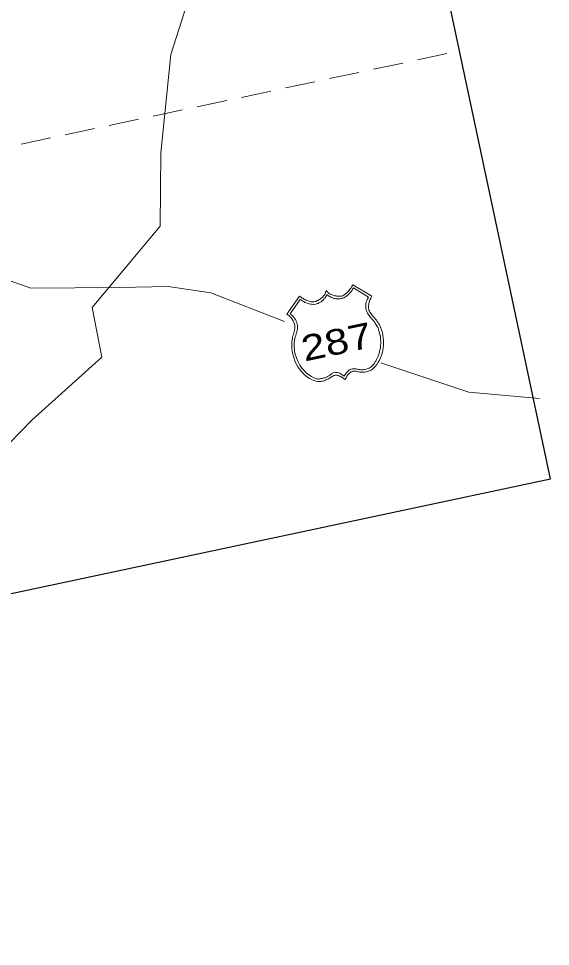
# Model space of a CAD drawing. Extents: x 2357218 to 2371708, y 6973728 to 6980157.
# Drawn here: x 2357673 to 2357779.4, y 6974407.9 to 6974593.4 of the extents above; entities that cross this region are included whole.
import ezdxf

# ---------------------------------------------------------------- set-up
doc = ezdxf.new("R2010")
doc.units = 0
doc.header["$LTSCALE"] = 2
doc.linetypes.add('MEDIUM_DASHED', pattern=[4.5, 3, -1.5])
doc.layers.add('62', color=7, linetype='Continuous', lineweight=13)
doc.layers.add('63', color=7, linetype='Continuous', lineweight=13)

msp = doc.modelspace()

# ---------------------------------------------------------------- linework, layer by layer
at = {"layer": '62', "linetype": 'MEDIUM_DASHED'}
msp.add_line((2357321.423, 6974493.477), (2357761.192, 6974586.953), dxfattribs=at)
at = {"layer": '62'}
for p, q in [((2357711.499, 6974538.57), (2357726.196, 6974532.859)), ((2357763.074, 6974518.776), (2357745.43, 6974524.617)), ((2357777.175, 6974517.491), (2357763.074, 6974518.776))]:
    msp.add_line(p, q, dxfattribs=at)
at = {"layer": '62', "lineweight": 25}
msp.add_lwpolyline([(2357242.867, 6974863.05), (2357339.603, 6974407.945), (2357779.37, 6974501.42), (2357682.634, 6974956.528)], dxfattribs=at)
at = {"layer": '62'}
for points in [[(2357711.499, 6974538.57), (2357702.972, 6974539.842), (2357693.168, 6974539.642), (2357675.502, 6974539.523), (2357664.168, 6974543.509), (2357656.491, 6974546.383), (2357646.543, 6974550.319), (2357635.988, 6974557.671), (2357627.86, 6974566.366), (2357619.672, 6974576.31), (2357608.58, 6974587.803), (2357599.534, 6974594.644), (2357592.196, 6974601.778), (2357583.834, 6974610.927), (2357578.923, 6974614.877), (2357569.363, 6974625.866)], [(2357712.856, 6974614.337), (2357709.274, 6974604.465), (2357703.489, 6974586.211), (2357701.445, 6974566.614), (2357701.343, 6974551.94), (2357687.74, 6974535.638), (2357689.697, 6974525.767), (2357675.675, 6974513.172), (2357664.632, 6974501.808), (2357650.419, 6974491.402), (2357629.375, 6974482.602), (2357611.62, 6974474.364), (2357592.404, 6974464.761), (2357580.771, 6974459.205)], [(2357726.648, 6974534.312), (2357729.214, 6974537.917), (2357729.429, 6974537.779), (2357729.646, 6974537.618), (2357729.876, 6974537.506), (2357730.068, 6974537.362), (2357730.302, 6974537.252), (2357730.505, 6974537.155), (2357730.708, 6974537.062), (2357730.934, 6974536.971), (2357731.108, 6974536.915), (2357731.324, 6974536.87), (2357731.519, 6974536.819), (2357731.728, 6974536.817), (2357731.913, 6974536.81), (2357732.074, 6974536.802), (2357732.296, 6974536.846), (2357732.494, 6974536.888), (2357732.617, 6974536.961), (2357732.76, 6974537.039), (2357732.932, 6974537.097), (2357733.094, 6974537.201), (2357733.258, 6974537.305), (2357733.392, 6974537.425), (2357733.556, 6974537.529), (2357733.711, 6974537.653), (2357733.838, 6974537.818), (2357733.986, 6974537.987), (2357734.112, 6974538.152), (2357734.242, 6974538.294), (2357734.32, 6974538.474), (2357734.418, 6974538.655), (2357734.443, 6974538.866), (2357734.52, 6974539.044), (2357734.662, 6974538.915), (2357734.815, 6974538.74), (2357734.984, 6974538.592), (2357735.145, 6974538.486), (2357735.333, 6974538.365), (2357735.535, 6974538.27), (2357735.712, 6974538.195), (2357735.912, 6974538.12), (2357736.109, 6974538.049), (2357736.289, 6974537.973), (2357736.518, 6974537.973), (2357736.693, 6974537.919), (2357736.943, 6974537.926), (2357737.107, 6974537.915), (2357737.336, 6974537.917), (2357737.518, 6974537.933), (2357737.671, 6974537.967), (2357737.863, 6974538.031), (2357737.983, 6974538.124), (2357738.169, 6974538.209), (2357738.333, 6974538.315), (2357738.468, 6974538.436), (2357738.605, 6974538.555), (2357738.779, 6974538.708), (2357738.905, 6974538.873), (2357739.056, 6974539.019), (2357739.178, 6974539.207), (2357739.347, 6974539.381), (2357739.471, 6974539.567), (2357739.607, 6974539.782), (2357739.725, 6974539.991), (2357739.868, 6974540.182), (2357743.683, 6974537.933), (2357743.461, 6974537.563), (2357743.241, 6974537.195), (2357743.121, 6974536.779), (2357743.052, 6974536.35), (2357742.977, 6974535.942), (2357742.979, 6974535.598), (2357743.042, 6974535.312), (2357743.084, 6974535.115), (2357743.167, 6974534.946), (2357743.275, 6974534.765), (2357743.377, 6974534.601), (2357743.512, 6974534.4), (2357743.668, 6974534.204), (2357743.826, 6974534.007), (2357744.011, 6974533.794), (2357744.193, 6974533.58), (2357744.381, 6974533.342), (2357744.565, 6974533.129), (2357744.736, 6974532.865), (2357744.897, 6974532.646), (2357745.036, 6974532.423), (2357745.175, 6974532.201), (2357745.298, 6974531.95), (2357745.392, 6974531.719), (2357745.576, 6974531.181), (2357745.762, 6974530.645), (2357745.867, 6974530.139), (2357745.913, 6974529.597), (2357745.982, 6974529.06), (2357745.997, 6974528.555), (2357745.967, 6974528.044), (2357745.915, 6974527.528), (2357745.861, 6974527.034), (2357745.738, 6974526.523)], [(2357744.731, 6974525.528), (2357744.882, 6974525.789), (2357744.994, 6974526.136), (2357745.103, 6974526.48), (2357745.209, 6974526.848), (2357745.289, 6974527.232), (2357745.364, 6974527.64), (2357745.417, 6974528.041), (2357745.436, 6974528.484), (2357745.454, 6974528.947), (2357745.408, 6974529.375), (2357745.374, 6974529.85), (2357745.28, 6974530.315), (2357745.154, 6974530.792), (2357745.02, 6974531.202), (2357744.893, 6974531.588), (2357744.713, 6974531.894), (2357744.548, 6974532.227), (2357744.351, 6974532.509), (2357744.181, 6974532.772), (2357743.987, 6974533.029), (2357743.777, 6974533.259), (2357743.568, 6974533.492), (2357743.388, 6974533.685), (2357743.227, 6974533.903), (2357743.066, 6974534.121), (2357742.898, 6974534.361), (2357742.787, 6974534.567), (2357742.669, 6974534.797), (2357742.568, 6974535.051), (2357742.481, 6974535.355), (2357742.477, 6974535.699), (2357742.473, 6974536.043), (2357742.491, 6974536.392), (2357742.548, 6974536.771), (2357742.663, 6974537.096), (2357742.823, 6974537.429), (2357742.981, 6974537.761), (2357739.973, 6974539.584), (2357739.853, 6974539.397), (2357739.751, 6974539.212), (2357739.636, 6974539.005), (2357739.509, 6974538.839), (2357739.368, 6974538.649), (2357739.213, 6974538.502), (2357739.062, 6974538.355), (2357738.908, 6974538.206), (2357738.733, 6974538.055), (2357738.581, 6974537.908), (2357738.395, 6974537.799), (2357738.231, 6974537.718), (2357738.067, 6974537.612), (2357737.919, 6974537.559), (2357737.771, 6974537.504), (2357737.619, 6974537.448), (2357737.462, 6974537.439), (2357737.279, 6974537.423), (2357737.084, 6974537.381), (2357736.917, 6974537.393), (2357736.684, 6974537.413), (2357736.521, 6974537.423), (2357736.33, 6974537.452), (2357736.114, 6974537.496), (2357735.941, 6974537.553), (2357735.724, 6974537.599), (2357735.57, 6974537.68), (2357735.387, 6974537.781), (2357735.188, 6974537.853), (2357735.024, 6974537.98), (2357734.859, 6974538.104), (2357734.69, 6974538.253), (2357734.589, 6974538.071), (2357734.496, 6974537.867), (2357734.386, 6974537.729), (2357734.281, 6974537.568), (2357734.147, 6974537.448), (2357734.059, 6974537.315), (2357733.907, 6974537.166), (2357733.794, 6974537.051), (2357733.654, 6974536.95), (2357733.497, 6974536.825), (2357733.373, 6974536.753), (2357733.208, 6974536.674), (2357733.063, 6974536.596), (2357732.922, 6974536.496), (2357732.746, 6974536.46), (2357732.603, 6974536.384), (2357732.451, 6974536.327), (2357732.232, 6974536.282), (2357732.02, 6974536.306), (2357731.795, 6974536.281), (2357731.6, 6974536.332), (2357731.365, 6974536.349), (2357731.129, 6974536.392), (2357730.949, 6974536.469), (2357730.707, 6974536.532), (2357730.481, 6974536.623), (2357730.281, 6974536.696), (2357730.087, 6974536.839), (2357729.864, 6974536.928), (2357729.67, 6974537.071)], [(2357729.352, 6974537.279), (2357727.333, 6974534.435), (2357727.672, 6974534.137), (2357727.966, 6974533.832), (2357728.191, 6974533.536), (2357728.41, 6974533.262), (2357728.545, 6974532.945), (2357728.672, 6974532.673), (2357728.75, 6974532.414), (2357728.796, 6974532.1), (2357728.791, 6974531.799), (2357728.802, 6974531.527), (2357728.77, 6974531.242), (2357728.693, 6974530.95), (2357728.641, 6974530.665), (2357728.564, 6974530.373), (2357728.464, 6974530.097), (2357728.363, 6974529.8), (2357728.199, 6974529.168), (2357728.133, 6974528.508), (2357728.104, 6974527.882), (2357728.178, 6974527.208), (2357728.292, 6974526.565), (2357728.454, 6974525.91), (2357728.704, 6974525.272), (2357728.968, 6974524.684), (2357729.297, 6974524.11), (2357729.692, 6974523.55), (2357730.118, 6974523.064), (2357730.561, 6974522.606), (2357731.054, 6974522.23), (2357731.566, 6974521.879), (2357732.103, 6974521.623), (2357732.63, 6974521.414), (2357732.749, 6974521.394), (2357732.896, 6974521.354), (2357733.055, 6974521.367), (2357733.231, 6974521.405), (2357733.367, 6974521.41), (2357733.545, 6974521.447), (2357733.721, 6974521.484), (2357733.897, 6974521.522), (2357734.09, 6974521.585), (2357734.244, 6974521.62), (2357734.431, 6974521.704), (2357734.604, 6974521.765), (2357734.75, 6974521.84), (2357734.916, 6974521.922), (2357735.057, 6974522.022), (2357735.183, 6974522.072), (2357735.297, 6974522.187), (2357735.435, 6974522.288), (2357735.534, 6974522.375), (2357735.672, 6974522.476), (2357735.817, 6974522.551), (2357735.945, 6974522.601), (2357736.089, 6974522.677), (2357736.243, 6974522.712), (2357736.407, 6974522.7), (2357736.616, 6974522.699), (2357736.799, 6974522.692), (2357737.002, 6974522.597), (2357737.253, 6974522.512), (2357737.518, 6974522.339), (2357737.829, 6974522.175), (2357738.128, 6974521.961), (2357738.353, 6974522.309), (2357738.566, 6974522.607), (2357738.769, 6974522.833), (2357738.981, 6974523.04), (2357739.155, 6974523.192), (2357739.343, 6974523.278), (2357739.51, 6974523.36), (2357739.731, 6974523.407), (2357739.885, 6974523.44), (2357740.047, 6974523.428), (2357740.254, 6974523.426), (2357740.444, 6974523.398), (2357740.619, 6974523.343), (2357740.807, 6974523.316), (2357741.02, 6974523.288), (2357741.238, 6974523.243), (2357741.449, 6974523.219), (2357741.659, 6974523.196), (2357741.863, 6974523.215), (2357742.084, 6974523.263), (2357742.288, 6974523.283), (2357742.503, 6974523.351), (2357742.7, 6974523.394), (2357742.91, 6974523.485), (2357743.122, 6974523.575), (2357743.305, 6974523.683), (2357743.503, 6974523.84), (2357743.682, 6974523.971), (2357743.851, 6974524.145), (2357744.045, 6974524.323), (2357744.183, 6974524.537), (2357744.338, 6974524.778), (2357744.482, 6974524.968), (2357744.607, 6974525.248), (2357744.731, 6974525.528)], [(2357729.67, 6974537.071), (2357729.511, 6974537.174), (2357729.352, 6974537.279)], [(2357727.447, 6974533.676), (2357727.104, 6974533.994), (2357726.648, 6974534.312)], [(2357745.738, 6974526.523), (2357745.584, 6974526.055), (2357745.378, 6974525.619), (2357745.203, 6974525.144), (2357744.902, 6974524.714), (2357744.649, 6974524.29), (2357744.319, 6974523.898), (2357744.131, 6974523.697), (2357743.963, 6974523.524), (2357743.763, 6974523.367), (2357743.563, 6974523.233), (2357743.384, 6974523.101), (2357743.167, 6974523.033), (2357742.935, 6974522.936), (2357742.748, 6974522.852), (2357742.503, 6974522.8), (2357742.282, 6974522.753), (2357742.082, 6974522.734), (2357741.901, 6974522.718), (2357741.668, 6974522.738), (2357741.481, 6974522.743), (2357741.296, 6974522.749), (2357741.101, 6974522.801), (2357740.912, 6974522.83), (2357740.721, 6974522.857), (2357740.575, 6974522.896), (2357740.386, 6974522.923), (2357740.248, 6974522.919), (2357740.062, 6974522.925), (2357739.879, 6974522.932), (2357739.727, 6974522.876), (2357739.56, 6974522.794), (2357739.377, 6974522.688), (2357739.224, 6974522.54), (2357739.05, 6974522.388), (2357738.861, 6974522.186), (2357738.684, 6974521.942), (2357738.498, 6974521.627), (2357738.295, 6974521.285), (2357737.972, 6974521.492), (2357737.709, 6974521.665), (2357737.462, 6974521.844), (2357737.21, 6974521.951), (2357737.028, 6974522.048), (2357736.833, 6974522.099), (2357736.664, 6974522.135), (2357736.503, 6974522.144), (2357736.365, 6974522.139), (2357736.21, 6974522.106), (2357736.079, 6974522.078), (2357735.936, 6974522.002), (2357735.836, 6974521.935), (2357735.684, 6974521.879), (2357735.55, 6974521.759), (2357735.426, 6974521.687), (2357735.309, 6974521.593), (2357735.164, 6974521.515), (2357735.002, 6974521.413), (2357734.812, 6974521.326), (2357734.645, 6974521.245), (2357734.452, 6974521.181), (2357734.264, 6974521.093), (2357734.099, 6974521.013), (2357733.878, 6974520.967), (2357733.679, 6974520.924), (2357733.479, 6974520.881), (2357733.23, 6974520.873), (2357733.02, 6974520.875), (2357732.787, 6974520.895), (2357732.549, 6974520.937), (2357732.305, 6974521), (2357731.728, 6974521.222), (2357731.154, 6974521.538), (2357730.599, 6974521.88), (2357730.117, 6974522.307), (2357729.649, 6974522.78), (2357729.241, 6974523.293), (2357728.896, 6974523.841), (2357728.56, 6974524.437), (2357728.271, 6974525.041), (2357728.047, 6974525.662), (2357727.863, 6974526.313), (2357727.725, 6974526.951), (2357727.656, 6974527.605), (2357727.637, 6974528.241), (2357727.682, 6974528.897), (2357727.784, 6974529.493), (2357727.825, 6974529.733), (2357727.884, 6974529.998), (2357727.97, 6974530.246), (2357728.045, 6974530.536), (2357728.124, 6974530.829), (2357728.197, 6974531.12), (2357728.252, 6974531.41), (2357728.256, 6974531.709), (2357728.257, 6974532.031), (2357728.188, 6974532.363), (2357728.095, 6974532.686), (2357727.937, 6974532.999), (2357727.726, 6974533.345), (2357727.447, 6974533.676)]]:
    msp.add_lwpolyline(points, dxfattribs=at)
at = {"layer": '63', "linetype": 'MEDIUM_DASHED'}
msp.add_line((2357321.423, 6974493.477), (2357761.192, 6974586.953), dxfattribs=at)
at = {"layer": '63'}
for p, q in [((2357711.499, 6974538.57), (2357726.196, 6974532.859)), ((2357763.074, 6974518.776), (2357745.43, 6974524.617)), ((2357777.175, 6974517.491), (2357763.074, 6974518.776))]:
    msp.add_line(p, q, dxfattribs=at)
at = {"layer": '63', "lineweight": 25}
msp.add_lwpolyline([(2357242.867, 6974863.05), (2357339.603, 6974407.945), (2357779.37, 6974501.42), (2357682.634, 6974956.528)], dxfattribs=at)
at = {"layer": '63'}
for points in [[(2357711.499, 6974538.57), (2357702.972, 6974539.842), (2357693.168, 6974539.642), (2357675.502, 6974539.523), (2357664.168, 6974543.509), (2357656.491, 6974546.383), (2357646.543, 6974550.319), (2357635.988, 6974557.671), (2357627.86, 6974566.366), (2357619.672, 6974576.31), (2357608.58, 6974587.803), (2357599.534, 6974594.644), (2357592.196, 6974601.778), (2357583.834, 6974610.927), (2357578.923, 6974614.877), (2357569.363, 6974625.866)], [(2357712.856, 6974614.337), (2357709.274, 6974604.465), (2357703.489, 6974586.211), (2357701.445, 6974566.614), (2357701.343, 6974551.94), (2357687.74, 6974535.638), (2357689.697, 6974525.767), (2357675.675, 6974513.172), (2357664.632, 6974501.808), (2357650.419, 6974491.402), (2357629.375, 6974482.602), (2357611.62, 6974474.364), (2357592.404, 6974464.761), (2357580.771, 6974459.205)], [(2357726.648, 6974534.312), (2357729.214, 6974537.917), (2357729.429, 6974537.779), (2357729.646, 6974537.618), (2357729.876, 6974537.506), (2357730.068, 6974537.362), (2357730.302, 6974537.252), (2357730.505, 6974537.155), (2357730.708, 6974537.062), (2357730.934, 6974536.971), (2357731.108, 6974536.915), (2357731.324, 6974536.87), (2357731.519, 6974536.819), (2357731.728, 6974536.817), (2357731.913, 6974536.81), (2357732.074, 6974536.802), (2357732.296, 6974536.846), (2357732.494, 6974536.888), (2357732.617, 6974536.961), (2357732.76, 6974537.039), (2357732.932, 6974537.097), (2357733.094, 6974537.201), (2357733.258, 6974537.305), (2357733.392, 6974537.425), (2357733.556, 6974537.529), (2357733.711, 6974537.653), (2357733.838, 6974537.818), (2357733.986, 6974537.987), (2357734.112, 6974538.152), (2357734.242, 6974538.294), (2357734.32, 6974538.474), (2357734.418, 6974538.655), (2357734.443, 6974538.866), (2357734.52, 6974539.044), (2357734.662, 6974538.915), (2357734.815, 6974538.74), (2357734.984, 6974538.592), (2357735.145, 6974538.486), (2357735.333, 6974538.365), (2357735.535, 6974538.27), (2357735.712, 6974538.195), (2357735.912, 6974538.12), (2357736.109, 6974538.049), (2357736.289, 6974537.973), (2357736.518, 6974537.973), (2357736.693, 6974537.919), (2357736.943, 6974537.926), (2357737.107, 6974537.915), (2357737.336, 6974537.917), (2357737.518, 6974537.933), (2357737.671, 6974537.967), (2357737.863, 6974538.031), (2357737.983, 6974538.124), (2357738.169, 6974538.209), (2357738.333, 6974538.315), (2357738.468, 6974538.436), (2357738.605, 6974538.555), (2357738.779, 6974538.708), (2357738.905, 6974538.873), (2357739.056, 6974539.019), (2357739.178, 6974539.207), (2357739.347, 6974539.381), (2357739.471, 6974539.567), (2357739.607, 6974539.782), (2357739.725, 6974539.991), (2357739.868, 6974540.182), (2357743.683, 6974537.933), (2357743.461, 6974537.563), (2357743.241, 6974537.195), (2357743.121, 6974536.779), (2357743.052, 6974536.35), (2357742.977, 6974535.942), (2357742.979, 6974535.598), (2357743.042, 6974535.312), (2357743.084, 6974535.115), (2357743.167, 6974534.946), (2357743.275, 6974534.765), (2357743.377, 6974534.601), (2357743.512, 6974534.4), (2357743.668, 6974534.204), (2357743.826, 6974534.007), (2357744.011, 6974533.794), (2357744.193, 6974533.58), (2357744.381, 6974533.342), (2357744.565, 6974533.129), (2357744.736, 6974532.865), (2357744.897, 6974532.646), (2357745.036, 6974532.423), (2357745.175, 6974532.201), (2357745.298, 6974531.95), (2357745.392, 6974531.719), (2357745.576, 6974531.181), (2357745.762, 6974530.645), (2357745.867, 6974530.139), (2357745.913, 6974529.597), (2357745.982, 6974529.06), (2357745.997, 6974528.555), (2357745.967, 6974528.044), (2357745.915, 6974527.528), (2357745.861, 6974527.034), (2357745.738, 6974526.523)], [(2357744.731, 6974525.528), (2357744.882, 6974525.789), (2357744.994, 6974526.136), (2357745.103, 6974526.48), (2357745.209, 6974526.848), (2357745.289, 6974527.232), (2357745.364, 6974527.64), (2357745.417, 6974528.041), (2357745.436, 6974528.484), (2357745.454, 6974528.947), (2357745.408, 6974529.375), (2357745.374, 6974529.85), (2357745.28, 6974530.315), (2357745.154, 6974530.792), (2357745.02, 6974531.202), (2357744.893, 6974531.588), (2357744.713, 6974531.894), (2357744.548, 6974532.227), (2357744.351, 6974532.509), (2357744.181, 6974532.772), (2357743.987, 6974533.029), (2357743.777, 6974533.259), (2357743.568, 6974533.492), (2357743.388, 6974533.685), (2357743.227, 6974533.903), (2357743.066, 6974534.121), (2357742.898, 6974534.361), (2357742.787, 6974534.567), (2357742.669, 6974534.797), (2357742.568, 6974535.051), (2357742.481, 6974535.355), (2357742.477, 6974535.699), (2357742.473, 6974536.043), (2357742.491, 6974536.392), (2357742.548, 6974536.771), (2357742.663, 6974537.096), (2357742.823, 6974537.429), (2357742.981, 6974537.761), (2357739.973, 6974539.584), (2357739.853, 6974539.397), (2357739.751, 6974539.212), (2357739.636, 6974539.005), (2357739.509, 6974538.839), (2357739.368, 6974538.649), (2357739.213, 6974538.502), (2357739.062, 6974538.355), (2357738.908, 6974538.206), (2357738.733, 6974538.055), (2357738.581, 6974537.908), (2357738.395, 6974537.799), (2357738.231, 6974537.718), (2357738.067, 6974537.612), (2357737.919, 6974537.559), (2357737.771, 6974537.504), (2357737.619, 6974537.448), (2357737.462, 6974537.439), (2357737.279, 6974537.423), (2357737.084, 6974537.381), (2357736.917, 6974537.393), (2357736.684, 6974537.413), (2357736.521, 6974537.423), (2357736.33, 6974537.452), (2357736.114, 6974537.496), (2357735.941, 6974537.553), (2357735.724, 6974537.599), (2357735.57, 6974537.68), (2357735.387, 6974537.781), (2357735.188, 6974537.853), (2357735.024, 6974537.98), (2357734.859, 6974538.104), (2357734.69, 6974538.253), (2357734.589, 6974538.071), (2357734.496, 6974537.867), (2357734.386, 6974537.729), (2357734.281, 6974537.568), (2357734.147, 6974537.448), (2357734.059, 6974537.315), (2357733.907, 6974537.166), (2357733.794, 6974537.051), (2357733.654, 6974536.95), (2357733.497, 6974536.825), (2357733.373, 6974536.753), (2357733.208, 6974536.674), (2357733.063, 6974536.596), (2357732.922, 6974536.496), (2357732.746, 6974536.46), (2357732.603, 6974536.384), (2357732.451, 6974536.327), (2357732.232, 6974536.282), (2357732.02, 6974536.306), (2357731.795, 6974536.281), (2357731.6, 6974536.332), (2357731.365, 6974536.349), (2357731.129, 6974536.392), (2357730.949, 6974536.469), (2357730.707, 6974536.532), (2357730.481, 6974536.623), (2357730.281, 6974536.696), (2357730.087, 6974536.839), (2357729.864, 6974536.928), (2357729.67, 6974537.071)], [(2357729.352, 6974537.279), (2357727.333, 6974534.435), (2357727.672, 6974534.137), (2357727.966, 6974533.832), (2357728.191, 6974533.536), (2357728.41, 6974533.262), (2357728.545, 6974532.945), (2357728.672, 6974532.673), (2357728.75, 6974532.414), (2357728.796, 6974532.1), (2357728.791, 6974531.799), (2357728.802, 6974531.527), (2357728.77, 6974531.242), (2357728.693, 6974530.95), (2357728.641, 6974530.665), (2357728.564, 6974530.373), (2357728.464, 6974530.097), (2357728.363, 6974529.8), (2357728.199, 6974529.168), (2357728.133, 6974528.508), (2357728.104, 6974527.882), (2357728.178, 6974527.208), (2357728.292, 6974526.565), (2357728.454, 6974525.91), (2357728.704, 6974525.272), (2357728.968, 6974524.684), (2357729.297, 6974524.11), (2357729.692, 6974523.55), (2357730.118, 6974523.064), (2357730.561, 6974522.606), (2357731.054, 6974522.23), (2357731.566, 6974521.879), (2357732.103, 6974521.623), (2357732.63, 6974521.414), (2357732.749, 6974521.394), (2357732.896, 6974521.354), (2357733.055, 6974521.367), (2357733.231, 6974521.405), (2357733.367, 6974521.41), (2357733.545, 6974521.447), (2357733.721, 6974521.484), (2357733.897, 6974521.522), (2357734.09, 6974521.585), (2357734.244, 6974521.62), (2357734.431, 6974521.704), (2357734.604, 6974521.765), (2357734.75, 6974521.84), (2357734.916, 6974521.922), (2357735.057, 6974522.022), (2357735.183, 6974522.072), (2357735.297, 6974522.187), (2357735.435, 6974522.288), (2357735.534, 6974522.375), (2357735.672, 6974522.476), (2357735.817, 6974522.551), (2357735.945, 6974522.601), (2357736.089, 6974522.677), (2357736.243, 6974522.712), (2357736.407, 6974522.7), (2357736.616, 6974522.699), (2357736.799, 6974522.692), (2357737.002, 6974522.597), (2357737.253, 6974522.512), (2357737.518, 6974522.339), (2357737.829, 6974522.175), (2357738.128, 6974521.961), (2357738.353, 6974522.309), (2357738.566, 6974522.607), (2357738.769, 6974522.833), (2357738.981, 6974523.04), (2357739.155, 6974523.192), (2357739.343, 6974523.278), (2357739.51, 6974523.36), (2357739.731, 6974523.407), (2357739.885, 6974523.44), (2357740.047, 6974523.428), (2357740.254, 6974523.426), (2357740.444, 6974523.398), (2357740.619, 6974523.343), (2357740.807, 6974523.316), (2357741.02, 6974523.288), (2357741.238, 6974523.243), (2357741.449, 6974523.219), (2357741.659, 6974523.196), (2357741.863, 6974523.215), (2357742.084, 6974523.263), (2357742.288, 6974523.283), (2357742.503, 6974523.351), (2357742.7, 6974523.394), (2357742.91, 6974523.485), (2357743.122, 6974523.575), (2357743.305, 6974523.683), (2357743.503, 6974523.84), (2357743.682, 6974523.971), (2357743.851, 6974524.145), (2357744.045, 6974524.323), (2357744.183, 6974524.537), (2357744.338, 6974524.778), (2357744.482, 6974524.968), (2357744.607, 6974525.248), (2357744.731, 6974525.528)], [(2357729.67, 6974537.071), (2357729.511, 6974537.174), (2357729.352, 6974537.279)], [(2357727.447, 6974533.676), (2357727.104, 6974533.994), (2357726.648, 6974534.312)], [(2357745.738, 6974526.523), (2357745.584, 6974526.055), (2357745.378, 6974525.619), (2357745.203, 6974525.144), (2357744.902, 6974524.714), (2357744.649, 6974524.29), (2357744.319, 6974523.898), (2357744.131, 6974523.697), (2357743.963, 6974523.524), (2357743.763, 6974523.367), (2357743.563, 6974523.233), (2357743.384, 6974523.101), (2357743.167, 6974523.033), (2357742.935, 6974522.936), (2357742.748, 6974522.852), (2357742.503, 6974522.8), (2357742.282, 6974522.753), (2357742.082, 6974522.734), (2357741.901, 6974522.718), (2357741.668, 6974522.738), (2357741.481, 6974522.743), (2357741.296, 6974522.749), (2357741.101, 6974522.801), (2357740.912, 6974522.83), (2357740.721, 6974522.857), (2357740.575, 6974522.896), (2357740.386, 6974522.923), (2357740.248, 6974522.919), (2357740.062, 6974522.925), (2357739.879, 6974522.932), (2357739.727, 6974522.876), (2357739.56, 6974522.794), (2357739.377, 6974522.688), (2357739.224, 6974522.54), (2357739.05, 6974522.388), (2357738.861, 6974522.186), (2357738.684, 6974521.942), (2357738.498, 6974521.627), (2357738.295, 6974521.285), (2357737.972, 6974521.492), (2357737.709, 6974521.665), (2357737.462, 6974521.844), (2357737.21, 6974521.951), (2357737.028, 6974522.048), (2357736.833, 6974522.099), (2357736.664, 6974522.135), (2357736.503, 6974522.144), (2357736.365, 6974522.139), (2357736.21, 6974522.106), (2357736.079, 6974522.078), (2357735.936, 6974522.002), (2357735.836, 6974521.935), (2357735.684, 6974521.879), (2357735.55, 6974521.759), (2357735.426, 6974521.687), (2357735.309, 6974521.593), (2357735.164, 6974521.515), (2357735.002, 6974521.413), (2357734.812, 6974521.326), (2357734.645, 6974521.245), (2357734.452, 6974521.181), (2357734.264, 6974521.093), (2357734.099, 6974521.013), (2357733.878, 6974520.967), (2357733.679, 6974520.924), (2357733.479, 6974520.881), (2357733.23, 6974520.873), (2357733.02, 6974520.875), (2357732.787, 6974520.895), (2357732.549, 6974520.937), (2357732.305, 6974521), (2357731.728, 6974521.222), (2357731.154, 6974521.538), (2357730.599, 6974521.88), (2357730.117, 6974522.307), (2357729.649, 6974522.78), (2357729.241, 6974523.293), (2357728.896, 6974523.841), (2357728.56, 6974524.437), (2357728.271, 6974525.041), (2357728.047, 6974525.662), (2357727.863, 6974526.313), (2357727.725, 6974526.951), (2357727.656, 6974527.605), (2357727.637, 6974528.241), (2357727.682, 6974528.897), (2357727.784, 6974529.493), (2357727.825, 6974529.733), (2357727.884, 6974529.998), (2357727.97, 6974530.246), (2357728.045, 6974530.536), (2357728.124, 6974530.829), (2357728.197, 6974531.12), (2357728.252, 6974531.41), (2357728.256, 6974531.709), (2357728.257, 6974532.031), (2357728.188, 6974532.363), (2357728.095, 6974532.686), (2357727.937, 6974532.999), (2357727.726, 6974533.345), (2357727.447, 6974533.676)]]:
    msp.add_lwpolyline(points, dxfattribs=at)

# ---------------------------------------------------------------- texts
at = {"layer": '62', "width": 1.25}
msp.add_text('287', height=5.099, rotation=12, dxfattribs=at).set_placement((2357730.198, 6974524.854))
at = {"layer": '63', "width": 1.25}
msp.add_text('287', height=5.099, rotation=12, dxfattribs=at).set_placement((2357730.198, 6974524.854))

doc.saveas('drawing.dxf')
